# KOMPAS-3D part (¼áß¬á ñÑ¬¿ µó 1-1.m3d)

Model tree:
1. Эскиз:1
2. Операция выдавливания:24
     Толщина стенки 2 = 14; Расстояние 1 = 0.6
3. Эскиз:22
4. Операция выдавливания:25
     Толщина стенки 1 = 7; Толщина стенки 2 = 6; Расстояние 1 = 0.6; Расстояние 2 = 0.6
5. Эскиз:23
6. Операция выдавливания:26
     Толщина стенки 1 = 6; Толщина стенки 2 = 6; Расстояние 1 = 0.6
7. Эскиз:26
8. Вырезать элемент выдавливания:3
     Толщина стенки 1 = 7; Расстояние 1 = 10
